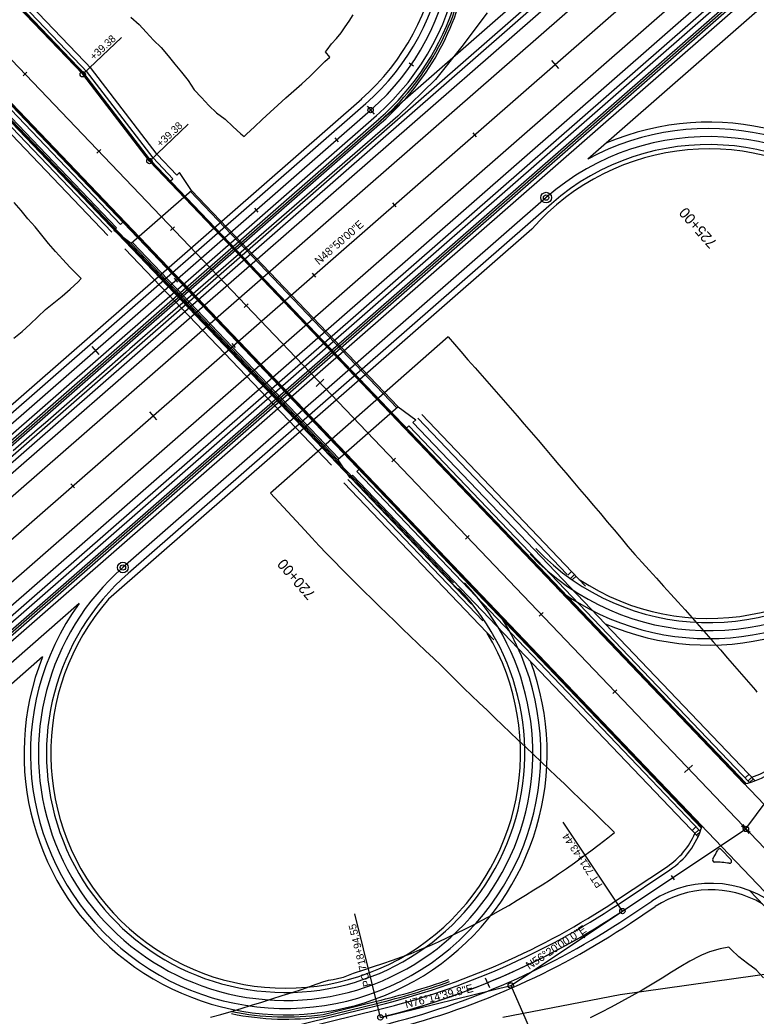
# Model space of a CAD drawing. Extents: x 1300404 to 1323571, y 234004 to 252077.
# Drawn here: x 1310561 to 1311251, y 240349 to 241283 of the extents above; entities that cross this region are included whole.
import ezdxf

# ---------------------------------------------------------------- set-up
doc = ezdxf.new("R2010")
doc.units = 0
for name, color, linetype in [('R_Barrier Wall', 7, 'Continuous'), ('R_Bridge', 7, 'Continuous'), ('R_Const Limits', 7, 'Continuous'), ('R_Curb', 7, 'Continuous'), ('R_Draft', 7, 'Continuous'), ('R_Flooplain', 7, 'Continuous'), ('R_Future', 7, 'Continuous'), ('R_Horz Alg Annot', 7, 'Continuous'), ('R_Horz Alg Annot Leader', 7, 'Continuous'), ('R_Horz Alg Major Ticks', 7, 'Continuous'), ('R_Horz Alg Minor Ticks', 7, 'Continuous'), ('R_Horz Alg Station Annot', 7, 'Continuous'), ('R_Horz Alg Tangents', 7, 'Continuous'), ('R_Horz Alg Tangents Text', 7, 'Continuous'), ('R_Lane Edge', 7, 'Continuous'), ('R_Proposed', 7, 'Continuous'), ('R_Shoulder', 7, 'Continuous'), ('R_Sidewalk Edge', 7, 'Continuous')]:
    doc.layers.add(name, color=color, linetype=linetype)

msp = doc.modelspace()

# ---------------------------------------------------------------- linework, layer by layer
at = {"layer": 'R_Barrier Wall'}
for p, q in [((1309593.62, 240046.84), (1310899.19, 241188.45)), ((1309594.93, 240045.34), (1310900.51, 241186.94))]:
    msp.add_line(p, q, dxfattribs=at)
for radius in [245, 247]:
    msp.add_arc((1310737.29, 241372.32), radius, 311.16667, 350.19245, dxfattribs=at)
at = {"layer": 'R_Bridge'}
for p, q in [((1310722.11, 241122.69), (1310710.82, 241139.47)), ((1310722.16, 241122.64), (1310665.52, 241073.12)), ((1310722.11, 241122.69), (1310915.62, 240919.95)), ((1310665.57, 241073.07), (1310649.24, 241085.22)), ((1310665.57, 241073.07), (1310859.08, 240870.34)), ((1310915.67, 240919.91), (1310859.03, 240870.38)), ((1310915.62, 240919.95), (1310931.95, 240907.8)), ((1310859.08, 240870.34), (1310870.37, 240853.55))]:
    msp.add_line(p, q, dxfattribs=at)
at = {"layer": 'R_Const Limits'}
msp.add_line((1310962.24, 240985.46), (1310796.06, 240839.06), dxfattribs=at)
for points in [[(1310998.78, 241289.24), (1310975.15, 241257.52), (1310950.38, 241226.7), (1310915.17, 241192.43), (1310664.29, 240974.18)], [(1310851.66, 241247.71), (1310847.34, 241252.65), (1310849.04, 241254.56), (1310853.19, 241260.09), (1310857.76, 241265.1), (1310862.04, 241270.34), (1310865.83, 241275.96), (1310869.6, 241281.54), (1310873.24, 241287.2)], [(1310665.31, 241285), (1310672.81, 241278.34), (1310679.66, 241271.06), (1310686.45, 241263.71), (1310693.56, 241256.67), (1310700.02, 241249.01), (1310706.3, 241241.18), (1310712.74, 241233.51), (1310719.01, 241225.67), (1310724.61, 241217.19), (1310731.28, 241209.74), (1310738.09, 241202.41), (1310745.34, 241195.5), (1310753.6, 241189.56), (1310760.84, 241182.65), (1310768.19, 241175.84), (1310771.22, 241173.42)], [(1310771.22, 241173.42), (1310773.57, 241175.53), (1310780.97, 241182.27), (1310788.25, 241189.13), (1310795.55, 241195.98), (1310802.91, 241202.76), (1310810.32, 241209.47), (1310817.8, 241216.11), (1310825.27, 241222.75), (1310832.67, 241229.49), (1310839.83, 241236.48), (1310847.01, 241243.47), (1310851.66, 241247.71)], [(1310618.57, 241040.13), (1310615.34, 241043.77), (1310608.12, 241050.7), (1310601.47, 241058.18), (1310594.67, 241065.51), (1310588.11, 241073.07), (1310581.76, 241080.84), (1310575.55, 241088.74), (1310568.7, 241096.02), (1310562.4, 241103.84), (1310555.79, 241111.35)], [(1310555.56, 240984.3), (1310563.36, 240990.58), (1310570.75, 240997.31), (1310577.94, 241004.28), (1310585.14, 241011.24), (1310592.99, 241017.46), (1310600.82, 241023.69), (1310608.32, 241030.3), (1310615.7, 241037.06), (1310618.57, 241040.13)], [(1310962.24, 240985.46), (1310974.29, 240971.67), (1310980.86, 240964.12), (1310987.5, 240956.62), (1310994.12, 240949.12), (1311000.74, 240941.61), (1311007.34, 240934.09), (1311013.93, 240926.55), (1311020.51, 240919.01), (1311027.07, 240911.45), (1311033.61, 240903.87), (1311040.12, 240896.26), (1311046.62, 240888.64), (1311053.11, 240881.01), (1311059.58, 240873.36), (1311066.04, 240865.7), (1311072.49, 240858.04), (1311079.01, 240850.44), (1311085.52, 240842.82), (1311092.01, 240835.19), (1311098.48, 240827.55), (1311104.95, 240819.89), (1311111.4, 240812.23), (1311117.83, 240804.55), (1311124.25, 240796.85), (1311130.69, 240789.18), (1311137.33, 240781.68), (1311143.98, 240774.21), (1311150.7, 240766.79), (1311157.4, 240759.37), (1311164.1, 240751.94), (1311170.8, 240744.52), (1311177.51, 240737.09), (1311184.21, 240729.66), (1311190.88, 240722.2), (1311197.49, 240714.69), (1311204.1, 240707.18), (1311210.71, 240699.66), (1311217.32, 240692.15), (1311223.87, 240684.57), (1311230.42, 240677), (1311236.97, 240669.43), (1311243.53, 240661.87), (1311250.13, 240654.34), (1311251.57, 240652.71)], [(1310664.29, 240974.18), (1310660.38, 240970.76), (1310652.86, 240964.18), (1310645.33, 240957.6), (1310637.8, 240951.02), (1310630.27, 240944.43), (1310622.74, 240937.85), (1310615.22, 240931.27), (1310607.69, 240924.69), (1310600.16, 240918.1), (1310592.63, 240911.52), (1310585.1, 240904.94), (1310577.58, 240898.36), (1310570.05, 240891.77), (1310562.52, 240885.19), (1310554.99, 240878.61)], [(1311118.12, 240520.92), (1311114.31, 240524.7), (1311107.2, 240531.74), (1311100.09, 240538.78), (1311092.99, 240545.82), (1311085.73, 240552.72), (1311078.47, 240559.61), (1311071.23, 240566.52), (1311063.94, 240573.4), (1311056.66, 240580.27), (1311049.38, 240587.14), (1311042.15, 240594.07), (1311034.96, 240601.02), (1311027.76, 240607.98), (1311020.51, 240614.89), (1311013.25, 240621.78), (1311005.99, 240628.67), (1310998.76, 240635.6), (1310991.55, 240642.54), (1310984.35, 240649.48), (1310977.15, 240656.44), (1310969.99, 240663.43), (1310962.84, 240670.43), (1310955.71, 240677.45), (1310948.51, 240684.39), (1310941.25, 240691.29), (1310934, 240698.2), (1310926.76, 240705.12), (1310919.54, 240712.05), (1310912.34, 240718.99), (1310905.14, 240725.95), (1310897.95, 240732.91), (1310890.78, 240739.89), (1310883.63, 240746.89), (1310876.6, 240754), (1310869.57, 240761.12), (1310862.52, 240768.21), (1310855.48, 240775.31), (1310848.45, 240782.43), (1310841.62, 240789.73), (1310834.81, 240797.06), (1310828.02, 240804.4), (1310796.06, 240839.06)], [(1310739.7, 240347.99), (1310749.35, 240350.62), (1310758.99, 240353.3), (1310768.57, 240356.23), (1310778.14, 240359.16), (1310787.72, 240362.11), (1310797.29, 240365.07), (1310806.82, 240368.2), (1310816.36, 240371.28), (1310825.91, 240374.33), (1310835.39, 240377.66), (1310844.84, 240381.09), (1310850.28, 240382.58), (1310854.61, 240383.25), (1310862.71, 240385.24), (1310864.32, 240385.64), (1310873.73, 240389.27), (1310883.23, 240392.49), (1310892.46, 240395.34), (1310901.33, 240398.3), (1310910.16, 240401.35), (1310918.93, 240404.52), (1310927.66, 240407.82), (1310936.29, 240411.33), (1310944.88, 240414.94), (1310953.39, 240418.69), (1310961.82, 240422.61), (1310970.21, 240426.58), (1310978.51, 240430.73), (1310986.77, 240434.92), (1310994.15, 240438.78), (1310994.96, 240439.23), (1311003.05, 240443.71), (1311011.12, 240448.19), (1311019.11, 240452.78), (1311026.96, 240457.62), (1311034.79, 240462.45), (1311042.65, 240467.2), (1311050.4, 240472.11), (1311058.07, 240477.13), (1311065.7, 240482.19), (1311073.21, 240487.44), (1311080.72, 240492.65), (1311088.03, 240498.14), (1311095.91, 240503.8), (1311103.87, 240509.89), (1311111.84, 240515.97), (1311118.12, 240520.92)], [(1311225.25, 240413.75), (1311217.03, 240412.16), (1311206.98, 240409.21), (1311199.76, 240406.26), (1311197.61, 240405.24), (1311188.77, 240400.46), (1311180.12, 240395.42), (1311171.6, 240390.16), (1311162.85, 240384.64), (1311153.44, 240378.89), (1311143.95, 240373.3), (1311134.35, 240367.9), (1311124.73, 240362.56), (1311115.02, 240357.38), (1311105.28, 240352.29), (1311095.43, 240347.39)], [(1311257.63, 240385.01), (1311250.71, 240392.23), (1311242.68, 240398.4), (1311234.66, 240404.57), (1311227.44, 240411.5), (1311225.25, 240413.75)]]:
    msp.add_lwpolyline(points, dxfattribs=at)
at = {"layer": 'R_Curb'}
for p, q in [((1310372.48, 241392.56), (1310671.99, 241078.77)), ((1310373.35, 241390.92), (1310671.61, 241078.44)), ((1310503.29, 241355.44), (1310622.23, 241230.84)), ((1310503.65, 241355.78), (1310622.61, 241231.16)), ((1310683.32, 241150.91), (1310620.85, 241232.28)), ((1310683.7, 241151.23), (1310621.23, 241232.61)), ((1310683.32, 241150.91), (1311065.94, 240750.04)), ((1310683.7, 241151.23), (1311067.92, 240748.69)), ((1310671.61, 241078.44), (1311009.39, 240724.57)), ((1310671.99, 241078.77), (1311008.13, 240726.61)), ((1311065.94, 240750.04), (1311240.77, 240566.88)), ((1311067.92, 240748.69), (1311241.33, 240567.02)), ((1311008.13, 240726.61), (1311199.82, 240525.78)), ((1311009.39, 240724.57), (1311199.65, 240525.24))]:
    msp.add_line(p, q, dxfattribs=at)
at = {"layer": 'R_Draft'}
for p, q in [((1308396.96, 238971.92), (1312368.36, 242444.53)), ((1308407.83, 238959.5), (1312379.22, 242432.11)), ((1308447.32, 238914.33), (1312418.71, 242386.94)), ((1308458.18, 238901.91), (1312429.57, 242374.52)), ((1309037.78, 239548.19), (1312137.61, 242258.71)), ((1309184.47, 239689.08), (1312131.36, 242265.86)), ((1309193.69, 239678.54), (1312140.58, 242255.32)), ((1309413.86, 239721.62), (1312065.67, 242040.38)), ((1309410.89, 239725), (1311987.97, 241978.41)), ((1309410.89, 239725), (1311987.97, 241978.41))]:
    msp.add_line(p, q, dxfattribs=at)
at = {"layer": 'R_Flooplain'}
for p, q in [((1311274.47, 240390.28), (1311123.39, 240368.86)), ((1311123.39, 240368.86), (1311013.46, 240347.78))]:
    msp.add_line(p, q, dxfattribs=at)
at = {"layer": 'R_Future'}
for p, q in [((1311714.76, 241726.24), (1309950.43, 240183.5)), ((1311716.07, 241724.73), (1309951.75, 240181.99)), ((1311717.39, 241723.23), (1309953.06, 240180.49)), ((1311720.02, 241720.22), (1309955.69, 240177.48)), ((1311729.9, 241708.92), (1311093.16, 241152.15)), ((1310504.53, 241233.21), (1310647.25, 241083.69)), ((1310506.77, 241235.21), (1310984.1, 240735.13)), ((1310506.77, 241235.21), (1310984.1, 240735.13)), ((1310507.13, 241235.55), (1310981.19, 240738.9)), ((1310507.13, 241235.55), (1310981.19, 240738.9)), ((1310507.86, 241236.24), (1310967.32, 240754.88)), ((1310507.86, 241236.24), (1310967.32, 240754.88)), ((1310500.78, 241229.89), (1310643.48, 241080.39)), ((1311054.08, 241115.99), (1310657.74, 240769.43)), ((1311059.02, 241110.35), (1310662.67, 240763.78)), ((1311040.69, 241086.35), (1310644.34, 240739.78)), ((1310659.55, 241067.9), (1310853.07, 240865.17)), ((1310933.94, 240909.34), (1311073.7, 240762.92)), ((1310937.71, 240912.63), (1311091.03, 240752)), ((1310864.62, 240848.72), (1311005.01, 240701.64)), ((1310868.38, 240852.02), (1310994.91, 240719.46)), ((1311074.39, 240762.19), (1311078.01, 240765.65)), ((1311077.15, 240759.3), (1311080.77, 240762.75)), ((1311078.53, 240757.85), (1311082.15, 240761.3)), ((1310616.69, 240735.53), (1309965.57, 240166.18)), ((1310582.45, 240685.67), (1309975.44, 240154.89)), ((1310845.18, 240350.66), (1310895.17, 240362.89)), ((1310845.56, 240348.69), (1310895.64, 240360.95))]:
    msp.add_line(p, q, dxfattribs=at)
for centre, radius in [((1311054.08, 241115.99), 5), ((1311054.08, 241115.99), 2.5), ((1310657.74, 240769.43), 5), ((1310657.74, 240769.43), 2.5)]:
    msp.add_circle(centre, radius, dxfattribs=at)
for centre, radius, start, end in [((1311206.47, 240941.72), 245, 246.68093, 113.15991), ((1311206.47, 240941.72), 239, 234.16397, 118.30111), ((1311206.47, 240941.72), 231.5, 223.66667, 131.16667), ((1311206.47, 240941.72), 231.5, 223.66667, 131.16667), ((1311206.47, 240941.72), 231.5, 223.66667, 131.16667), ((1311206.47, 240941.72), 231.5, 223.66667, 131.16667), ((1311206.47, 240941.72), 224, 223.66667, 131.16667), ((1311206.47, 240941.72), 220, 236.50529, 138.89832), ((1310810.12, 240595.16), 231.5, 131.16667, 43.66667), ((1310810.12, 240595.16), 231.5, 131.16667, 43.66667), ((1310810.12, 240595.16), 231.5, 131.16667, 43.66667), ((1310810.12, 240595.16), 231.5, 131.16667, 43.66667), ((1310810.12, 240595.16), 224, 131.16667, 43.66667), ((1310810.12, 240595.16), 220, 138.89832, 30.82805), ((1310810.12, 240595.16), 239, 144.03223, 33.16936), ((1310810.12, 240595.16), 245, 158.31916, 20.65241), ((1310728.55, 241043.5), 700.7, 283.75562, 289.5516), ((1310728.55, 241043.5), 702.7, 283.75562, 289.5516), ((1310810.12, 240595.16), 247, 258.26431, 278.16053), ((1310810.12, 240595.16), 249, 258.26431, 278.18307)]:
    msp.add_arc(centre, radius, start, end, dxfattribs=at)
at = {"layer": 'R_Horz Alg Annot Leader'}
for p, q in [((1310620.08, 241231.63), (1310656.29, 241266.19)), ((1310682.55, 241150.26), (1310718.76, 241184.81))]:
    msp.add_line(p, q, dxfattribs=at)
for points in [[(1311125.58, 240447.42), (1311070.15, 240530.65)], [(1310898.85, 240347.84), (1310875.07, 240444.97)], [(1311020.96, 240377.73), (1311061.17, 240286.17)]]:
    msp.add_lwpolyline(points, dxfattribs=at)
at = {"layer": 'R_Horz Alg Major Ticks'}
for points in [[(1311059.07, 241244.55), (1311065.65, 241237.03)], [(1310886.38, 241201.81), (1310892.96, 241194.29)], [(1310886.38, 241201.81), (1310892.96, 241194.29)], [(1310886.38, 241201.81), (1310892.96, 241194.29)], [(1310628.68, 240976.48), (1310635.27, 240968.95)], [(1310845.86, 240945.85), (1310838.63, 240938.95)], [(1310682.67, 240915.43), (1310689.26, 240907.9)], [(1311191.09, 240584.17), (1311183.86, 240577.26)], [(1311237.17, 240527.39), (1311245.23, 240521.47)], [(1311237.17, 240527.39), (1311245.23, 240521.47)], [(1311238.43, 240528.59), (1311243.97, 240520.27)], [(1310997.17, 240384.98), (1311000.95, 240375.72)]]:
    msp.add_lwpolyline(points, dxfattribs=at)
at = {"layer": 'R_Horz Alg Minor Ticks'}
for points in [[(1310925.88, 241242.42), (1310930, 241239.59)], [(1310567.87, 241233.47), (1310564.25, 241230.02)], [(1310985.44, 241176.85), (1310988.73, 241173.08)], [(1310856.17, 241172.08), (1310859.46, 241168.31)], [(1310636.92, 241161.14), (1310633.3, 241157.68)], [(1310910.16, 241111.02), (1310913.45, 241107.26)], [(1310780.89, 241106.25), (1310784.18, 241102.49)], [(1310705.96, 241088.8), (1310702.35, 241085.35)], [(1310834.88, 241045.2), (1310838.17, 241041.43)], [(1310705.61, 241040.43), (1310708.9, 241036.66)], [(1310775.01, 241016.46), (1310771.39, 241013.01)], [(1310759.6, 240979.37), (1310762.89, 240975.61)], [(1310913.1, 240871.79), (1310909.48, 240868.34)], [(1310609.04, 240847.72), (1310612.33, 240843.96)], [(1310982.15, 240799.45), (1310978.53, 240796)], [(1311051.19, 240727.11), (1311047.58, 240723.66)], [(1311120.24, 240654.78), (1311116.62, 240651.33)], [(1311171.27, 240480.86), (1311174.04, 240476.69)], [(1311087.46, 240426.61), (1311089.98, 240422.29)], [(1310903.52, 240351.58), (1310904.75, 240346.73)]]:
    msp.add_lwpolyline(points, dxfattribs=at)
at = {"layer": 'R_Horz Alg Tangents'}
for p, q in [((1311020.96, 240377.73), (1311125.58, 240447.42)), ((1310898.85, 240347.84), (1311020.96, 240377.73))]:
    msp.add_line(p, q, dxfattribs=at)
at = {"layer": 'R_Lane Edge'}
for p, q in [((1310412.25, 241352.34), (1311200.16, 240526.88)), ((1310502.57, 241354.75), (1310620.08, 241231.63)), ((1310682.55, 241150.26), (1310620.08, 241231.63)), ((1309579.79, 240062.65), (1310885.34, 241204.23)), ((1309589.67, 240051.36), (1310895.24, 241192.96)), ((1310682.55, 241150.26), (1311239.63, 240566.63)), ((1311218.13, 240505.15), (1311227.3, 240495.54)), ((1311121.43, 240453.66), (1311169.87, 240485.93)), ((1311129.74, 240441.18), (1311152.96, 240456.64)), ((1310159.85, 240174.65), (1310897.07, 240355.12))]:
    msp.add_line(p, q, dxfattribs=at)
for centre, radius, start, end in [((1310737.29, 241372.32), 239, 311.16667, 114.47385), ((1310737.29, 241372.32), 224, 311.16667, 114.47385), ((1311223.73, 240639.92), 75, 282.23981, 323.66667), ((1311128.3, 240548.35), 75, 303.66667, 343.36241), ((1311128.3, 240548.35), 97, 327.64047, 333.23281), ((1311216.69, 240503.77), 2, 43.66667, 153.2328), ((1311211.92, 240495.36), 2, 147.6397, 268.34378), ((1311208.4, 240373.42), 120, 81.77128, 88.34378), ((1311225.86, 240494.16), 2, 261.77107, 43.66667), ((1311208.4, 240373.42), 100, 43.66667, 123.66667), ((1310728.55, 241043.5), 708.7, 283.75562, 303.66667), ((1310728.55, 241043.5), 723.7, 283.75562, 303.66667)]:
    msp.add_arc(centre, radius, start, end, dxfattribs=at)
at = {"layer": 'R_Proposed'}
for p, q in [((1308463.14, 238968.01), (1312793.8, 242754.77)), ((1308427.57, 238936.91), (1312398.96, 242409.52)), ((1309180.37, 239595.16), (1312398.96, 242409.52)), ((1309180.37, 239595.16), (1312398.96, 242409.52)), ((1309180.37, 239595.16), (1312051.46, 242105.66)), ((1310151.78, 241665.77), (1311952.58, 239779.15)), ((1310165.59, 241651.3), (1311952.63, 239779.09)), ((1310165.59, 241651.3), (1311952.63, 239779.09)), ((1310223.05, 241550.56), (1311374.36, 240344.37)), ((1310502.57, 241354.75), (1310620.08, 241231.63)), ((1310620.08, 241231.63), (1310682.55, 241150.26)), ((1309584.71, 240056.98), (1310889.67, 241198.05)), ((1310682.55, 241150.26), (1311414.87, 240383.04)), ((1311241.2, 240524.43), (1311372.02, 240702.3)), ((1311241.2, 240524.43), (1311372.02, 240702.3)), ((1311241.2, 240524.43), (1311372.02, 240702.3)), ((1311125.58, 240447.42), (1311241.2, 240524.43)), ((1311125.58, 240447.42), (1311241.2, 240524.43)), ((1311125.58, 240447.42), (1311241.2, 240524.43)), ((1311125.58, 240447.42), (1311241.2, 240524.43)), ((1311125.58, 240447.42), (1311241.2, 240524.43))]:
    msp.add_line(p, q, dxfattribs=at)
for centre in [(1310620.08, 241231.63), (1310889.67, 241198.05), (1310889.67, 241198.05), (1310682.55, 241150.26), (1311241.2, 240524.43), (1311241.2, 240524.43), (1311125.58, 240447.42), (1311020.96, 240377.73), (1310898.85, 240347.84)]:
    msp.add_circle(centre, 2.5, dxfattribs=at)
for centre, radius, start, end in [((1310737.29, 241372.32), 231.5, 311.16667, 114.47385), ((1310728.55, 241043.5), 716.2, 283.75562, 303.66667), ((1310728.55, 241043.5), 716.2, 283.75562, 303.66667), ((1310728.55, 241043.5), 716.2, 284.21185, 303.66667), ((1310728.55, 241043.5), 716.2, 284.21185, 303.66667), ((1310728.55, 241043.5), 716.2, 284.21185, 303.66667)]:
    msp.add_arc(centre, radius, start, end, dxfattribs=at)
at = {"layer": 'R_Shoulder'}
for p, q in [((1309575.85, 240067.17), (1310881.38, 241208.74)), ((1309592.3, 240048.35), (1310897.87, 241189.95)), ((1311119.21, 240456.99), (1311167.66, 240489.26)), ((1311133.07, 240436.19), (1311156.29, 240451.65)), ((1310158.9, 240178.54), (1310896.12, 240359.01))]:
    msp.add_line(p, q, dxfattribs=at)
for centre, radius, start, end in [((1310737.29, 241372.32), 243, 311.16667, 77.31825), ((1310737.29, 241372.32), 218, 311.16667, 114.47385), ((1311223.73, 240639.92), 71, 289.02247, 323.66667), ((1311128.3, 240548.35), 71, 303.66667, 336.59012), ((1311208.4, 240373.42), 94, 59.35095, 123.66667), ((1310728.55, 241043.5), 704.7, 283.75562, 303.66667), ((1310728.55, 241043.5), 729.7, 283.75562, 303.66667)]:
    msp.add_arc(centre, radius, start, end, dxfattribs=at)
at = {"layer": 'R_Sidewalk Edge'}
for p, q in [((1310480.07, 241392.08), (1310628.7, 241236.37)), ((1310378.2, 241381.49), (1310655.54, 241090.93)), ((1310485.35, 241379.31), (1310624.89, 241233.12)), ((1310385.11, 241367.02), (1310651.77, 241087.64)), ((1310685.98, 241153.18), (1310623.51, 241234.56)), ((1310689.79, 241156.44), (1310627.32, 241237.82)), ((1310689.79, 241156.44), (1310708.13, 241137.21)), ((1310685.98, 241153.18), (1310704.52, 241133.76)), ((1310710.82, 241139.47), (1310708.29, 241137.06)), ((1310702.35, 241131.69), (1310704.52, 241133.76)), ((1310720.92, 241121.65), (1310914.43, 240918.91)), ((1310655.54, 241090.93), (1310657.71, 241093.01)), ((1310651.77, 241087.64), (1310649.24, 241085.22)), ((1310666.76, 241074.11), (1310860.27, 240871.38)), ((1310931.95, 240907.8), (1310929.42, 240905.39)), ((1310929.42, 240905.39), (1311249.89, 240569.63)), ((1310923.48, 240900.02), (1310925.65, 240902.09)), ((1310925.65, 240902.09), (1311244.64, 240567.9)), ((1310876.67, 240859.26), (1310878.84, 240861.33)), ((1310876.67, 240859.26), (1311198.54, 240522.06)), ((1310872.9, 240855.97), (1310870.37, 240853.55)), ((1310872.9, 240855.97), (1311196.44, 240517.02)), ((1311240.5, 240572.24), (1311244.12, 240575.69)), ((1311243.26, 240569.34), (1311246.88, 240572.8)), ((1311244.64, 240567.9), (1311248.26, 240571.35)), ((1311190.78, 240522.95), (1311194.39, 240526.4)), ((1311193.54, 240520.05), (1311197.16, 240523.51)), ((1311194.92, 240518.61), (1311198.54, 240522.06)), ((1311244.49, 240466.68), (1311367.53, 240337.77))]:
    msp.add_line(p, q, dxfattribs=at)

# ---------------------------------------------------------------- texts
at = {"layer": 'R_Horz Alg Annot'}
for s, rotation, p in [('+39.38', 43.07689, (1310630.68, 241244.32)), ('+39.38', 43.07689, (1310693.15, 241162.94)), ('PT 721+43.44', 123.66667, (1311107.38, 240472.05)), ('PC 718+94.55', 103.75562, (1310890.03, 240377.58))]:
    msp.add_text(s, height=7, rotation=rotation, dxfattribs=at).set_placement(p)
at = {"layer": 'R_Horz Alg Station Annot'}
for s, p in [('725+00', (1311214.87, 241073.98)), ('720+00', (1310838.65, 240744.64))]:
    msp.add_text(s, height=10, rotation=131.16667, dxfattribs=at).set_placement(p)
at = {"layer": 'R_Horz Alg Tangents Text'}
for s, rotation, p in [('N48%%d50\'00"E', 41.16667, (1310841.31, 241052.54)), ('N56%%d20\'00.0"E', 33.66667, (1311038.32, 240392.3)), ('N76%%d14\'39.8"E', 13.75562, (1310923.02, 240356.33))]:
    msp.add_text(s, height=7.5, rotation=rotation, dxfattribs=at).set_placement(p)

doc.saveas('drawing.dxf')
